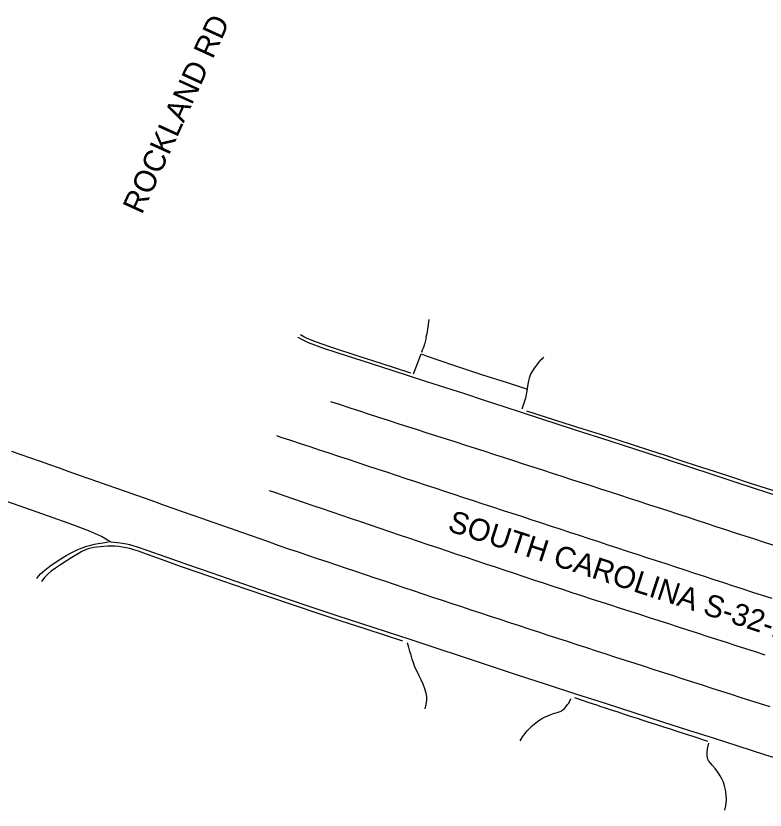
# Model space of a CAD drawing. Extents: x 1961683 to 1977751, y 798292 to 805767.
# Drawn here: x 1964179.5 to 1964364.3, y 799292.7 to 799488.7 of the extents above; entities that cross this region are included whole.
import ezdxf

# ---------------------------------------------------------------- set-up
doc = ezdxf.new("R2010")
doc.units = 0
for name, color, linetype in [('RD_EX_Road', 7, 'Continuous'), ('RD_EX_Road_Paint', 7, 'Continuous'), ('RD_TX_RoadID', 7, 'Continuous')]:
    doc.layers.add(name, color=color, linetype=linetype)

msp = doc.modelspace()

# ---------------------------------------------------------------- linework, layer by layer
at = {"layer": 'RD_EX_Road'}
for points in [[(1964281.37, 799413.74), (1964281.29, 799413.16), (1964281.2, 799412.55), (1964281.11, 799411.96), (1964281.01, 799411.37), (1964280.91, 799410.8), (1964280.81, 799410.25), (1964280.72, 799409.77), (1964280.64, 799409.33), (1964280.58, 799408.95), (1964280.52, 799408.6), (1964280.43, 799408.24), (1964280.33, 799407.88), (1964280.21, 799407.51), (1964280.07, 799407.11), (1964279.91, 799406.66), (1964279.73, 799406.16), (1964279.54, 799405.6)], [(1964276.94, 799400.56), (1964269.59, 799402.92), (1964263.89, 799404.76), (1964257.43, 799406.86), (1964254.78, 799407.74), (1964253.19, 799408.31), (1964252.18, 799408.71), (1964251.31, 799409.1), (1964250.51, 799409.53), (1964249.69, 799410.02)], [(1964370.81, 799369.09), (1964361.68, 799372.08), (1964356.6, 799373.75), (1964351.18, 799375.54), (1964345.7, 799377.34), (1964340.45, 799379.06), (1964335.44, 799380.69), (1964326.06, 799383.71), (1964317.3, 799386.54), (1964308.95, 799389.27), (1964299.9, 799392.22), (1964295.06, 799393.8), (1964290.18, 799395.39), (1964280.88, 799398.4), (1964272.28, 799401.16), (1964264.93, 799403.54), (1964259.01, 799405.46), (1964255.17, 799406.73), (1964253.26, 799407.4), (1964251.69, 799408.03), (1964250.22, 799408.71), (1964249.09, 799409.32)], [(1964277.6, 799400.35), (1964277.91, 799401.17), (1964278.55, 799402.87), (1964279.44, 799405.31), (1964280.69, 799404.81), (1964287.4, 799402.49), (1964294.34, 799400.2), (1964300.62, 799398.23), (1964304.44, 799396.95), (1964305.61, 799396.56), (1964305.19, 799394.33), (1964304.28, 799391.63)], [(1964309.62, 799404.44), (1964309.17, 799404.02), (1964308.74, 799403.57), (1964308.33, 799403.09), (1964307.94, 799402.61), (1964307.57, 799402.12), (1964307.23, 799401.63), (1964306.92, 799401.14), (1964306.65, 799400.68), (1964306.43, 799400.24), (1964306.25, 799399.82), (1964306.1, 799399.33), (1964305.94, 799398.65), (1964305.79, 799397.78), (1964305.63, 799396.73)], [(1964378.07, 799367.65), (1964371.69, 799369.74), (1964365.89, 799371.63), (1964360.68, 799373.34), (1964356.05, 799374.84), (1964351.78, 799376.24), (1964347.63, 799377.59), (1964343.6, 799378.91), (1964339.69, 799380.19), (1964335.8, 799381.46), (1964331.84, 799382.75), (1964327.8, 799384.05), (1964323.69, 799385.36), (1964319.44, 799386.72), (1964315, 799388.13), (1964310.37, 799389.61), (1964305.55, 799391.14)], [(1964371.89, 799303.95), (1964364.23, 799306.37), (1964357.61, 799308.51), (1964351.52, 799310.48), (1964345.47, 799312.4), (1964339.07, 799314.42), (1964331.96, 799316.7), (1964324.65, 799319.07), (1964317.63, 799321.34), (1964310.6, 799323.62), (1964303.24, 799326.02), (1964296.02, 799328.39), (1964289.41, 799330.58), (1964283.15, 799332.66), (1964276.98, 799334.7), (1964270.88, 799336.7), (1964264.85, 799338.65), (1964258.77, 799340.64), (1964252.55, 799342.73), (1964246.21, 799344.88), (1964239.77, 799347.06), (1964233.56, 799349.19), (1964227.89, 799351.16), (1964222.37, 799353.11), (1964216.6, 799355.12), (1964211.89, 799356.76), (1964209.52, 799357.59), (1964208.45, 799357.95), (1964207.6, 799358.18), (1964206.79, 799358.34), (1964205.82, 799358.52), (1964204.58, 799358.7), (1964202.95, 799358.86), (1964200.59, 799360.19), (1964197.65, 799361.51), (1964193.52, 799363.09), (1964187.58, 799365.22), (1964180.28, 799367.79), (1964172.03, 799370.7)], [(1964184.68, 799349.9), (1964184.74, 799349.99), (1964185.6, 799350.99), (1964186.65, 799351.94), (1964187.88, 799352.9), (1964189.21, 799353.83), (1964190.56, 799354.71), (1964191.94, 799355.54), (1964193.32, 799356.31), (1964194.65, 799356.97), (1964195.87, 799357.47), (1964196.98, 799357.84), (1964197.96, 799358.11), (1964198.89, 799358.31), (1964199.82, 799358.48), (1964200.92, 799358.66), (1964202.34, 799358.87)], [(1964274.97, 799334.41), (1964265.91, 799337.34), (1964259.47, 799339.44), (1964254.09, 799341.23), (1964248.22, 799343.2), (1964242.17, 799345.25), (1964236.26, 799347.26), (1964230.57, 799349.22), (1964225.17, 799351.07), (1964220.09, 799352.85), (1964215.41, 799354.55), (1964211.74, 799355.9), (1964209.74, 799356.61), (1964208.62, 799356.97), (1964207.62, 799357.25), (1964206.68, 799357.47), (1964205.76, 799357.63), (1964204.86, 799357.74), (1964203.99, 799357.81), (1964203.08, 799357.84), (1964202.12, 799357.81), (1964201.17, 799357.75), (1964200.3, 799357.7), (1964199.5, 799357.63), (1964198.71, 799357.51), (1964197.98, 799357.36), (1964197.34, 799357.19), (1964196.66, 799356.93), (1964195.78, 799356.51), (1964194.69, 799355.9), (1964193.34, 799355.07), (1964191.9, 799354.15), (1964190.52, 799353.26), (1964189.27, 799352.42), (1964188.25, 799351.67), (1964187.39, 799350.93), (1964186.64, 799350.17), (1964186.02, 799349.41), (1964185.82, 799349.11)], [(1964280.44, 799317.68), (1964280.71, 799318.79), (1964280.85, 799319.82), (1964280.85, 799320.71), (1964280.69, 799321.59), (1964280.36, 799322.64), (1964279.94, 799323.76), (1964279.46, 799324.85), (1964278.97, 799325.86), (1964278.52, 799326.73), (1964278.13, 799327.51), (1964277.82, 799328.24), (1964277.55, 799329.03), (1964277.25, 799329.98), (1964276.95, 799330.96), (1964276.66, 799331.87), (1964276.38, 799332.83), (1964276.1, 799333.95)], [(1964303.85, 799309.78), (1964304.08, 799310.23), (1964304.49, 799310.91), (1964304.99, 799311.57), (1964305.57, 799312.24), (1964306.21, 799312.92), (1964306.93, 799313.61), (1964307.72, 799314.28), (1964308.44, 799314.82), (1964309.1, 799315.24), (1964309.89, 799315.65), (1964310.83, 799316.06), (1964311.87, 799316.44), (1964312.96, 799316.78), (1964313.73, 799317.05), (1964313.97, 799317.16), (1964314.17, 799317.27), (1964314.37, 799317.42), (1964314.77, 799317.82), (1964315.17, 799318.28), (1964315.57, 799318.76), (1964315.77, 799319.03), (1964316.18, 799319.77), (1964316.39, 799320.24)], [(1964350.18, 799309.66), (1964346.77, 799310.77), (1964344.39, 799311.55), (1964342.59, 799312.13), (1964340.9, 799312.68), (1964339.32, 799313.19), (1964337.84, 799313.67), (1964336.46, 799314.12), (1964335.16, 799314.53), (1964333.94, 799314.93), (1964332.77, 799315.31), (1964331.66, 799315.67), (1964330.6, 799316.01), (1964329.6, 799316.34), (1964328.66, 799316.64), (1964327.75, 799316.94), (1964326.84, 799317.24), (1964325.9, 799317.55), (1964324.91, 799317.87), (1964323.86, 799318.22), (1964322.76, 799318.59), (1964320.84, 799319.22), (1964317.33, 799320.39)], [(1964354.35, 799292.72), (1964354.57, 799293.8), (1964354.71, 799295.22), (1964354.68, 799296.51), (1964354.5, 799297.7), (1964354.26, 799298.73), (1964353.97, 799299.59), (1964353.62, 799300.4), (1964353.2, 799301.19), (1964352.64, 799302.05), (1964351.96, 799302.98), (1964351.25, 799303.83), (1964350.56, 799304.6), (1964350.31, 799304.95), (1964350.14, 799305.28), (1964350.04, 799305.59), (1964349.96, 799306.22), (1964349.94, 799306.9), (1964350.05, 799307.83), (1964350.37, 799309.24)]]:
    msp.add_lwpolyline(points, dxfattribs=at)
at = {"layer": 'RD_EX_Road_Paint'}
for points in [[(1964257.09, 799393.55), (1964259.47, 799392.77), (1964261.84, 799391.99), (1964264.21, 799391.22), (1964266.59, 799390.44), (1964268.97, 799389.67), (1964271.34, 799388.91), (1964273.72, 799388.14), (1964276.1, 799387.37), (1964278.48, 799386.61), (1964280.85, 799385.84), (1964283.23, 799385.08), (1964285.61, 799384.31), (1964287.99, 799383.55), (1964290.36, 799382.78), (1964292.74, 799382.02), (1964295.12, 799381.25), (1964297.5, 799380.48), (1964299.88, 799379.72), (1964302.25, 799378.95), (1964304.63, 799378.19), (1964307.01, 799377.42), (1964309.38, 799376.64), (1964311.76, 799375.87), (1964314.14, 799375.1), (1964316.51, 799374.33), (1964318.89, 799373.56), (1964321.26, 799372.79), (1964323.64, 799372.01), (1964326.02, 799371.24), (1964328.39, 799370.47), (1964330.77, 799369.7), (1964333.15, 799368.93), (1964335.52, 799368.16), (1964337.9, 799367.38), (1964340.27, 799366.61), (1964342.65, 799365.84), (1964345.02, 799365.06), (1964347.4, 799364.28), (1964349.77, 799363.5), (1964352.15, 799362.72), (1964354.52, 799361.95), (1964356.9, 799361.17), (1964359.27, 799360.39), (1964361.64, 799359.61), (1964364.02, 799358.83), (1964366.39, 799358.05)], [(1964365.97, 799344.93), (1964363.59, 799345.69), (1964361.21, 799346.45), (1964358.84, 799347.22), (1964356.46, 799347.99), (1964354.09, 799348.77), (1964351.71, 799349.55), (1964349.34, 799350.33), (1964346.97, 799351.11), (1964344.59, 799351.89), (1964342.22, 799352.67), (1964339.84, 799353.45), (1964337.47, 799354.22), (1964335.1, 799355), (1964332.72, 799355.78), (1964330.35, 799356.56), (1964327.98, 799357.34), (1964325.6, 799358.12), (1964323.23, 799358.9), (1964320.85, 799359.68), (1964318.48, 799360.45), (1964316.11, 799361.23), (1964313.73, 799362.01), (1964311.36, 799362.79), (1964308.98, 799363.57), (1964306.61, 799364.35), (1964304.24, 799365.13), (1964301.86, 799365.91), (1964299.49, 799366.68), (1964297.12, 799367.46), (1964294.74, 799368.24), (1964292.37, 799369.02), (1964289.99, 799369.8), (1964287.62, 799370.58), (1964285.25, 799371.36), (1964282.87, 799372.14), (1964280.5, 799372.92), (1964278.13, 799373.7), (1964275.76, 799374.49), (1964273.38, 799375.27), (1964271.01, 799376.06), (1964268.64, 799376.84), (1964266.27, 799377.62), (1964263.9, 799378.41), (1964261.53, 799379.19), (1964259.15, 799379.98), (1964256.78, 799380.76), (1964254.41, 799381.55), (1964252.04, 799382.33), (1964249.67, 799383.12), (1964247.3, 799383.9), (1964244.92, 799384.69), (1964243.88, 799385.03)], [(1964365.48, 799318.16), (1964363.1, 799318.93), (1964360.73, 799319.7), (1964358.35, 799320.46), (1964355.97, 799321.23), (1964353.59, 799321.99), (1964351.21, 799322.76), (1964348.83, 799323.52), (1964346.46, 799324.29), (1964344.08, 799325.05), (1964341.7, 799325.82), (1964339.32, 799326.59), (1964336.94, 799327.35), (1964334.56, 799328.12), (1964332.19, 799328.88), (1964329.81, 799329.65), (1964327.43, 799330.41), (1964325.05, 799331.18), (1964322.67, 799331.95), (1964320.3, 799332.73), (1964317.93, 799333.51), (1964315.55, 799334.29), (1964313.18, 799335.07), (1964310.81, 799335.84), (1964308.43, 799336.62), (1964306.06, 799337.4), (1964303.68, 799338.18), (1964301.31, 799338.96), (1964298.94, 799339.74), (1964296.56, 799340.52), (1964294.19, 799341.3), (1964291.82, 799342.08), (1964289.44, 799342.86), (1964287.07, 799343.64), (1964284.7, 799344.42), (1964282.33, 799345.21), (1964279.96, 799346.01), (1964277.59, 799346.8), (1964275.22, 799347.6), (1964272.86, 799348.39), (1964270.49, 799349.19), (1964268.12, 799349.98), (1964265.75, 799350.78), (1964263.38, 799351.57), (1964261.01, 799352.37), (1964258.65, 799353.16), (1964256.28, 799353.96), (1964253.91, 799354.75), (1964251.54, 799355.55), (1964249.17, 799356.34), (1964246.81, 799357.14), (1964244.45, 799357.96), (1964242.09, 799358.79), (1964239.73, 799359.62), (1964237.38, 799360.45), (1964235.02, 799361.27), (1964232.66, 799362.1), (1964230.31, 799362.93), (1964227.95, 799363.76), (1964225.6, 799364.59), (1964223.24, 799365.42), (1964220.88, 799366.25), (1964218.53, 799367.08), (1964216.17, 799367.91), (1964213.81, 799368.74), (1964211.46, 799369.57), (1964209.1, 799370.4), (1964206.75, 799371.23), (1964204.39, 799372.06), (1964202.04, 799372.89), (1964199.68, 799373.72), (1964197.33, 799374.56), (1964194.97, 799375.39), (1964192.62, 799376.22), (1964190.26, 799377.05), (1964187.91, 799377.88), (1964185.55, 799378.71), (1964183.2, 799379.55), (1964180.84, 799380.38), (1964178.49, 799381.21)], [(1964364.27, 799330.98), (1964361.89, 799331.75), (1964359.51, 799332.51), (1964357.13, 799333.27), (1964354.75, 799334.04), (1964352.38, 799334.8), (1964350, 799335.57), (1964347.62, 799336.34), (1964345.24, 799337.11), (1964342.87, 799337.88), (1964340.49, 799338.64), (1964338.11, 799339.41), (1964335.73, 799340.18), (1964333.36, 799340.95), (1964330.98, 799341.71), (1964328.6, 799342.48), (1964326.22, 799343.25), (1964323.85, 799344.02), (1964321.47, 799344.79), (1964319.09, 799345.55), (1964316.72, 799346.34), (1964314.35, 799347.13), (1964311.98, 799347.91), (1964309.61, 799348.7), (1964307.24, 799349.49), (1964304.87, 799350.28), (1964302.5, 799351.07), (1964300.13, 799351.86), (1964297.76, 799352.65), (1964295.39, 799353.44), (1964293.02, 799354.23), (1964290.65, 799355.02), (1964288.28, 799355.81), (1964285.91, 799356.6), (1964283.54, 799357.39), (1964281.17, 799358.18), (1964278.8, 799358.98), (1964276.43, 799359.78), (1964274.07, 799360.59), (1964271.7, 799361.39), (1964269.34, 799362.2), (1964266.97, 799363), (1964264.61, 799363.81), (1964262.25, 799364.61), (1964259.88, 799365.42), (1964257.52, 799366.22), (1964255.15, 799367.03), (1964252.79, 799367.83), (1964250.42, 799368.64), (1964248.06, 799369.44), (1964245.69, 799370.25), (1964243.33, 799371.05), (1964242.08, 799371.48)]]:
    msp.add_lwpolyline(points, dxfattribs=at)

# ---------------------------------------------------------------- texts
at = {"layer": 'RD_TX_RoadID'}
for s, rotation, p in [('ROCKLAND RD', 65.5134, (1964210.57, 799439.49)), ('SOUTH CAROLINA S-32-107 bush river', 341.9453, (1964285.73, 799361.69))]:
    msp.add_text(s, height=5.4, rotation=rotation, dxfattribs=at).set_placement(p)

doc.saveas('drawing.dxf')
